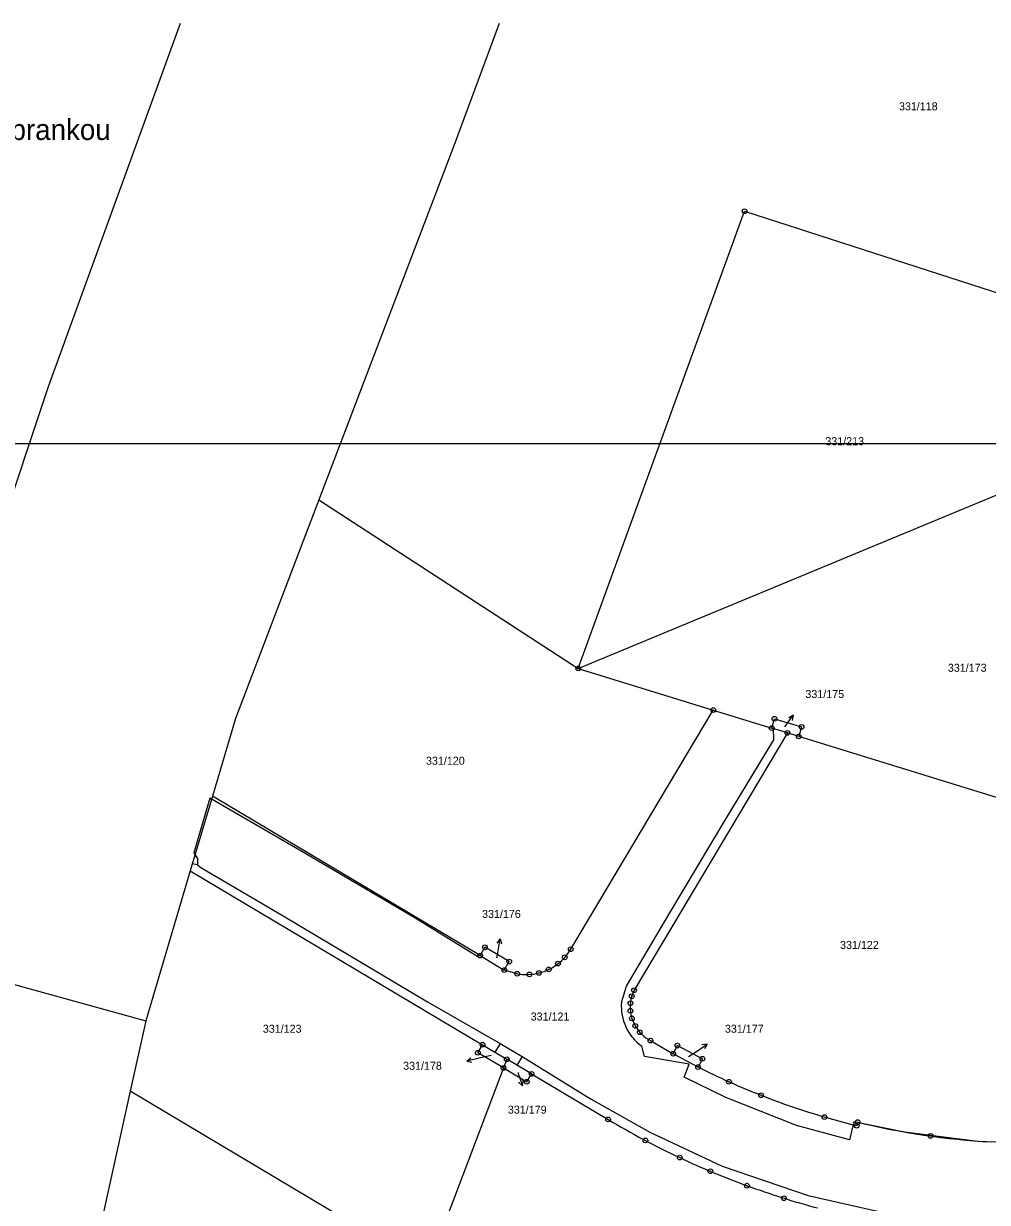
# Model space of a CAD drawing. Extents: x -770973 to -770265, y -1049936 to -1049427.
# Drawn here: x -770840.3 to -770738, y -1049553.2 to -1049428.1 of the extents above; entities that cross this region are included whole.
import ezdxf

# ---------------------------------------------------------------- set-up
doc = ezdxf.new("R2010")
doc.units = 0
for name, color, linetype in [('Vrstva 1', 7, 'Continuous'), ('Vrstva 13', 7, 'Continuous'), ('Vrstva 14', 7, 'Continuous'), ('Vrstva 16', 7, 'Continuous'), ('Vrstva 28', 7, 'Continuous'), ('Vrstva 39', 7, 'Continuous'), ('Vrstva 50', 7, 'Continuous'), ('Vrstva 63', 7, 'Continuous')]:
    doc.layers.add(name, color=color, linetype=linetype)

msp = doc.modelspace()

# ---------------------------------------------------------------- linework, layer by layer
at = {"layer": 'Vrstva 1'}
for p, q in [((-770823.69, -1049428.06), (-770837.69, -1049466.63)), ((-770789.8, -1049428.06), (-770794.61, -1049441.03)), ((-770794.61, -1049441.03), (-770808.96, -1049478.64)), ((-770781.42, -1049496.53), (-770763.77, -1049447.98)), ((-770763.77, -1049447.98), (-770707.08, -1049466.34)), ((-770837.69, -1049466.63), (-770857.36, -1049525.64)), ((-770781.42, -1049496.53), (-770708.89, -1049466.46)), ((-770808.96, -1049478.64), (-770817.81, -1049501.84)), ((-770808.96, -1049478.64), (-770781.42, -1049496.53)), ((-770781.42, -1049496.53), (-770767.09, -1049500.95)), ((-770817.81, -1049501.84), (-770820.26, -1049510.09)), ((-770782.22, -1049526.35), (-770767.09, -1049500.95)), ((-770767.09, -1049500.95), (-770760.89, -1049502.87)), ((-770760.89, -1049502.87), (-770760.59, -1049501.88)), ((-770760.59, -1049501.88), (-770757.72, -1049502.75)), ((-770759.22, -1049503.38), (-770775.49, -1049530.71)), ((-770759.22, -1049503.38), (-770760.89, -1049502.87)), ((-770758.02, -1049503.75), (-770759.22, -1049503.38)), ((-770757.72, -1049502.75), (-770758.02, -1049503.75)), ((-770725.13, -1049513.91), (-770758.02, -1049503.75)), ((-770820.26, -1049510.09), (-770822.6, -1049518.01)), ((-770791.84, -1049527.02), (-770820.26, -1049510.09)), ((-770822.6, -1049518.01), (-770827.33, -1049533.95)), ((-770822.6, -1049518.01), (-770791.58, -1049536.5)), ((-770857.36, -1049525.64), (-770827.33, -1049533.95)), ((-770791.33, -1049526.15), (-770791.84, -1049527.02)), ((-770791.84, -1049527.02), (-770789.27, -1049528.56)), ((-770788.74, -1049527.66), (-770791.33, -1049526.15)), ((-770789.27, -1049528.56), (-770788.74, -1049527.66)), ((-770787.9, -1049528.96), (-770789.27, -1049528.56)), ((-770827.33, -1049533.95), (-770828.98, -1049541.44)), ((-770775.73, -1049533.69), (-770775.37, -1049534.49)), ((-770792.08, -1049537.34), (-770791.58, -1049536.5)), ((-770791.58, -1049536.5), (-770789.01, -1049538.03)), ((-770773.76, -1049536.05), (-770771.34, -1049537.45)), ((-770771.34, -1049537.45), (-770770.9, -1049536.59)), ((-770770.9, -1049536.59), (-770768.24, -1049537.98)), ((-770789.36, -1049538.96), (-770792.08, -1049537.34)), ((-770789.01, -1049538.03), (-770789.36, -1049538.96)), ((-770786.38, -1049539.59), (-770789.01, -1049538.03)), ((-770768.7, -1049538.86), (-770771.34, -1049537.45)), ((-770768.24, -1049537.98), (-770768.7, -1049538.86)), ((-770789.36, -1049538.96), (-770797.43, -1049560.23)), ((-770789.36, -1049538.96), (-770786.89, -1049540.43)), ((-770786.89, -1049540.43), (-770786.38, -1049539.59)), ((-770786.38, -1049539.59), (-770778.25, -1049544.43)), ((-770828.98, -1049541.44), (-770836.54, -1049575.8)), ((-770806.02, -1049555.11), (-770828.98, -1049541.44)), ((-770751.86, -1049545.09), (-770751.77, -1049544.7))]:
    msp.add_line(p, q, dxfattribs=at)
for centre, radius, start, end in [((-770786.89, -1049523.59), 5.43, 307.7412, 329.4115), ((-770786.85, -1049523.74), 5.28, 283.8115, 308.4073), ((-770786.96, -1049523.52), 5.52, 260.1472, 284.3151), ((-770771.73, -1049532.55), 4.19, 153.9574, 173.7136), ((-770771.81, -1049532.49), 4.1, 174.4007, 197.0205), ((-770771.87, -1049532.49), 4.03, 209.7465, 242.0608), ((-770734.33, -1049471.26), 75.83, 243.0476, 248.5825), ((-770733.43, -1049469.52), 77.78, 248.4342, 256.2935), ((-770733.34, -1049469.31), 87.52, 239.1269, 244.7673), ((-770733.4, -1049469.63), 77.29, 256.2526, 266.8876), ((-770733.93, -1049470.55), 86.15, 244.7723, 249.9197), ((-770732.15, -1049465.46), 91.54, 249.963, 254.8759)]:
    msp.add_arc(centre, radius, start, end, dxfattribs=at)
at = {"layer": 'Vrstva 13'}
for p, q in [((-770790.06, -1049527.27), (-770789.97, -1049526.73)), ((-770790.66, -1049537.65), (-770791.78, -1049537.9)), ((-770769.71, -1049537.74), (-770768.99, -1049537.27))]:
    msp.add_line(p, q, dxfattribs=at)
at = {"layer": 'Vrstva 16'}
for p, q in [((-770759.5, -1049502.73), (-770758.62, -1049501.51)), ((-770758.62, -1049501.51), (-770759.12, -1049501.77)), ((-770758.62, -1049501.51), (-770758.71, -1049502.06)), ((-770789.72, -1049525.25), (-770790.05, -1049525.7)), ((-770789.97, -1049526.73), (-770789.72, -1049525.25)), ((-770789.72, -1049525.25), (-770789.55, -1049525.79)), ((-770768.99, -1049537.27), (-770767.73, -1049536.45)), ((-770767.73, -1049536.45), (-770768.29, -1049536.51)), ((-770767.73, -1049536.45), (-770768.02, -1049536.93)), ((-770793.24, -1049538.23), (-770792.81, -1049537.88)), ((-770791.78, -1049537.9), (-770793.24, -1049538.23)), ((-770793.24, -1049538.23), (-770792.7, -1049538.36)), ((-770787.85, -1049539.43), (-770787.34, -1049540.84)), ((-770787.34, -1049540.84), (-770787.75, -1049540.46)), ((-770787.34, -1049540.84), (-770787.28, -1049540.29))]:
    msp.add_line(p, q, dxfattribs=at)
at = {"layer": 'Vrstva 28'}
for centre, radius in [((-770763.77, -1049447.98), 0.25), ((-770763.77, -1049447.98), 0.005), ((-770781.42, -1049496.53), 0.25), ((-770781.42, -1049496.53), 0.005), ((-770767.09, -1049500.95), 0.25), ((-770767.09, -1049500.95), 0.005), ((-770760.59, -1049501.88), 0.25), ((-770760.59, -1049501.88), 0.005), ((-770760.89, -1049502.87), 0.25), ((-770760.89, -1049502.87), 0.005), ((-770759.22, -1049503.38), 0.25), ((-770759.22, -1049503.38), 0.005), ((-770757.72, -1049502.75), 0.25), ((-770757.72, -1049502.75), 0.005), ((-770758.02, -1049503.75), 0.25), ((-770758.02, -1049503.75), 0.005), ((-770791.33, -1049526.15), 0.25), ((-770791.84, -1049527.02), 0.25), ((-770791.84, -1049527.02), 0.005), ((-770791.33, -1049526.15), 0.005), ((-770782.85, -1049527.21), 0.25), ((-770782.85, -1049527.21), 0.005), ((-770782.22, -1049526.35), 0.25), ((-770782.22, -1049526.35), 0.005), ((-770789.27, -1049528.56), 0.25), ((-770788.74, -1049527.66), 0.25), ((-770788.74, -1049527.66), 0.005), ((-770784.56, -1049528.5), 0.25), ((-770783.57, -1049527.88), 0.25), ((-770783.57, -1049527.88), 0.005), ((-770789.27, -1049528.56), 0.005), ((-770787.9, -1049528.96), 0.25), ((-770787.9, -1049528.96), 0.005), ((-770786.6, -1049529.03), 0.25), ((-770786.6, -1049529.03), 0.005), ((-770785.59, -1049528.87), 0.25), ((-770785.59, -1049528.87), 0.005), ((-770784.56, -1049528.5), 0.005), ((-770775.49, -1049530.71), 0.25), ((-770775.49, -1049530.71), 0.005), ((-770775.89, -1049532.09), 0.25), ((-770775.74, -1049531.35), 0.25), ((-770775.89, -1049532.09), 0.005), ((-770775.74, -1049531.35), 0.005), ((-770775.89, -1049532.89), 0.25), ((-770775.73, -1049533.69), 0.25), ((-770775.89, -1049532.89), 0.005), ((-770775.73, -1049533.69), 0.005), ((-770775.37, -1049534.49), 0.25), ((-770775.37, -1049534.49), 0.005), ((-770774.89, -1049535.16), 0.25), ((-770774.89, -1049535.16), 0.005), ((-770773.76, -1049536.05), 0.25), ((-770792.08, -1049537.34), 0.25), ((-770791.58, -1049536.5), 0.25), ((-770791.58, -1049536.5), 0.005), ((-770773.76, -1049536.05), 0.005), ((-770771.34, -1049537.45), 0.25), ((-770770.9, -1049536.59), 0.25), ((-770770.9, -1049536.59), 0.005), ((-770792.08, -1049537.34), 0.005), ((-770789.01, -1049538.03), 0.25), ((-770789.01, -1049538.03), 0.005), ((-770771.34, -1049537.45), 0.005), ((-770768.24, -1049537.98), 0.25), ((-770768.24, -1049537.98), 0.005), ((-770789.36, -1049538.96), 0.25), ((-770789.36, -1049538.96), 0.005), ((-770786.38, -1049539.59), 0.25), ((-770786.38, -1049539.59), 0.005), ((-770768.7, -1049538.86), 0.25), ((-770768.7, -1049538.86), 0.005), ((-770786.89, -1049540.43), 0.25), ((-770786.89, -1049540.43), 0.005), ((-770765.42, -1049540.43), 0.25), ((-770765.42, -1049540.43), 0.005), ((-770762.02, -1049541.86), 0.25), ((-770762.02, -1049541.86), 0.005), ((-770778.25, -1049544.43), 0.25), ((-770778.25, -1049544.43), 0.005), ((-770755.29, -1049544.17), 0.25), ((-770755.29, -1049544.17), 0.005), ((-770751.77, -1049544.7), 0.25), ((-770751.77, -1049544.7), 0.005), ((-770751.86, -1049545.09), 0.25), ((-770751.86, -1049545.09), 0.005), ((-770744.03, -1049546.18), 0.25), ((-770774.29, -1049546.66), 0.25), ((-770774.29, -1049546.66), 0.005), ((-770744.03, -1049546.18), 0.005), ((-770770.65, -1049548.48), 0.25), ((-770770.65, -1049548.48), 0.005), ((-770767.4, -1049549.93), 0.25), ((-770767.4, -1049549.93), 0.005), ((-770763.51, -1049551.46), 0.25), ((-770763.51, -1049551.46), 0.005), ((-770759.59, -1049552.79), 0.25), ((-770759.59, -1049552.79), 0.005)]:
    msp.add_circle(centre, radius, dxfattribs=at)
at = {"layer": 'Vrstva 50'}
for p, q in [((-770760.67, -1049504.1), (-770760.69, -1049502.94)), ((-770765.82, -1049512.66), (-770760.67, -1049504.1)), ((-770820.51, -1049510.32), (-770822.24, -1049516.12)), ((-770810.77, -1049515.99), (-770820.51, -1049510.32)), ((-770771.71, -1049522.47), (-770765.82, -1049512.66)), ((-770822.24, -1049516.12), (-770821.83, -1049516.71)), ((-770821.83, -1049516.71), (-770821.84, -1049517.39)), ((-770798.83, -1049523), (-770810.77, -1049515.99)), ((-770821.84, -1049517.39), (-770822.41, -1049517.28)), ((-770821.84, -1049517.39), (-770821.47, -1049517.67)), ((-770821.47, -1049517.67), (-770812.73, -1049522.79)), ((-770812.73, -1049522.79), (-770797.42, -1049531.92)), ((-770792.07, -1049527.17), (-770798.83, -1049523)), ((-770776.3, -1049530.29), (-770771.71, -1049522.47)), ((-770791.96, -1049527), (-770792.07, -1049527.17)), ((-770776.83, -1049532.01), (-770776.3, -1049530.29)), ((-770797.42, -1049531.92), (-770789.72, -1049536.37)), ((-770789.72, -1049536.37), (-770790.32, -1049537.35)), ((-770789.72, -1049536.37), (-770787.36, -1049537.73)), ((-770774.4, -1049537.73), (-770774.68, -1049536.64)), ((-770787.36, -1049537.73), (-770787.99, -1049538.75)), ((-770787.36, -1049537.73), (-770780.06, -1049542.26)), ((-770769.65, -1049538.54), (-770774.4, -1049537.73)), ((-770770.17, -1049539.95), (-770769.65, -1049538.54)), ((-770765.75, -1049542.11), (-770770.17, -1049539.95)), ((-770758.24, -1049545.08), (-770765.75, -1049542.11)), ((-770780.06, -1049542.26), (-770773.82, -1049545.79)), ((-770752.16, -1049544.67), (-770752.64, -1049546.59)), ((-770746.8, -1049545.76), (-770752.16, -1049544.67)), ((-770773.82, -1049545.79), (-770766.16, -1049549.38)), ((-770752.64, -1049546.59), (-770758.24, -1049545.08)), ((-770739, -1049546.78), (-770746.8, -1049545.76)), ((-770733.22, -1049546.96), (-770739, -1049546.78)), ((-770766.16, -1049549.38), (-770757, -1049552.5)), ((-770757, -1049552.5), (-770747.13, -1049554.72))]:
    msp.add_line(p, q, dxfattribs=at)
msp.add_arc((-770771.63, -1049532.41), 5.22, 175.6275, 234.1893, dxfattribs=at)
at = {"layer": 'Vrstva 63'}
msp.add_lwpolyline([(-770858.67, -1049892.7), (-770264.67, -1049892.7), (-770264.67, -1049472.7), (-770858.67, -1049472.7), (-770858.67, -1049892.7)], dxfattribs=at)

# ---------------------------------------------------------------- texts
at = {"layer": 'Vrstva 14'}
for s, height, p in [('331/118', 0.85, (-770747.38, -1049437.27)), ('331/213', 0.85, (-770755.19, -1049472.83)), ('331/173', 0.85, (-770742.19, -1049496.89)), ('331/175', 0.05, (-770759.5, -1049502.73)), ('331/120', 0.85, (-770797.58, -1049506.76)), ('331/122', 0.85, (-770753.63, -1049526.32)), ('331/176', 0.05, (-770790.06, -1049527.27)), ('331/121', 0.85, (-770786.47, -1049533.92)), ('331/123', 0.85, (-770814.9, -1049535.22)), ('331/178', 0.05, (-770790.66, -1049537.65)), ('331/177', 0.05, (-770769.71, -1049537.74)), ('331/179', 0.05, (-770787.85, -1049539.43))]:
    msp.add_text(s, height=height, dxfattribs=at).set_placement(p)
at = {"layer": 'Vrstva 16'}
for s, p in [('331/175', (-770757.31, -1049499.68)), ('331/176', (-770791.63, -1049523.03)), ('331/177', (-770765.85, -1049535.22)), ('331/178', (-770800.01, -1049539.15)), ('331/179', (-770788.89, -1049543.81))]:
    msp.add_text(s, height=0.85, dxfattribs=at).set_placement(p)
at = {"layer": 'Vrstva 39'}
msp.add_text('Za brankou', height=2.2, dxfattribs=at).set_placement((-770845.93, -1049440.42))

doc.saveas('drawing.dxf')
